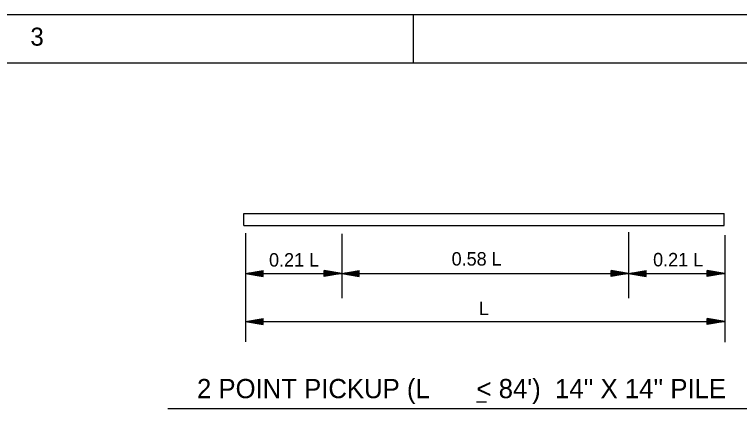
# Model space of a CAD drawing. Extents: x 22369.62 to 22373.29, y 22366.31 to 22369.14.
# Drawn here: x 22371.361 to 22371.989, y 22368.783 to 22369.142 of the extents above; entities that cross this region are included whole.
import ezdxf

# ---------------------------------------------------------------- set-up
doc = ezdxf.new("R2010")
doc.units = 0
for name, color, linetype in [('Level 1', 7, 'Continuous'), ('Level 10', 7, 'Continuous'), ('Level 2', 7, 'Continuous'), ('Level 3', 7, 'Continuous'), ('Level 4', 7, 'Continuous'), ('Level 9', 7, 'Continuous')]:
    doc.layers.add(name, color=color, linetype=linetype)

msp = doc.modelspace()

# ---------------------------------------------------------------- linework, layer by layer
at = {"layer": 'Level 1'}
msp.add_lwpolyline([(22369.6213, 22369.14218), (22373.2867, 22369.14218), (22373.2867, 22366.30818), (22369.6213, 22366.30818)], close=True, dxfattribs=at)
at = {"layer": 'Level 10'}
msp.add_line((22371.7067, 22369.10017), (22371.7067, 22369.14218), dxfattribs=at)
at = {"layer": 'Level 2'}
for p, q in [((22371.55968, 22368.96982), (22371.97617, 22368.96982)), ((22371.55968, 22368.9594), (22371.55968, 22368.96982)), ((22371.97617, 22368.9594), (22371.97617, 22368.96982)), ((22371.55968, 22368.9594), (22371.97617, 22368.9594)), ((22371.76143, 22368.8065), (22371.77014, 22368.8065)), ((22371.49399, 22368.80084), (22372.05537, 22368.80084))]:
    msp.add_line(p, q, dxfattribs=at)
at = {"layer": 'Level 3'}
for p, q in [((22371.56127, 22368.95271), (22371.56127, 22368.85863)), ((22371.64457, 22368.95209), (22371.64457, 22368.89644)), ((22371.8933, 22368.95359), (22371.8933, 22368.89637)), ((22371.9766, 22368.951), (22371.9766, 22368.8583)), ((22371.56127, 22368.91776), (22371.57651, 22368.92034)), ((22371.56127, 22368.91776), (22371.9766, 22368.91776)), ((22371.56127, 22368.91776), (22371.57651, 22368.91776)), ((22371.56127, 22368.91776), (22371.57651, 22368.91516)), ((22371.56406, 22368.91797), (22371.57584, 22368.91997)), ((22371.57619, 22368.91811), (22371.56406, 22368.91797)), ((22371.57619, 22368.91738), (22371.56406, 22368.91753)), ((22371.56406, 22368.91753), (22371.57584, 22368.91554)), ((22371.56741, 22368.91828), (22371.57549, 22368.91961)), ((22371.57582, 22368.91842), (22371.56741, 22368.91828)), ((22371.56741, 22368.91722), (22371.57549, 22368.91588)), ((22371.57582, 22368.91707), (22371.56741, 22368.91722)), ((22371.57065, 22368.91855), (22371.57516, 22368.91924)), ((22371.57548, 22368.91871), (22371.57065, 22368.91855)), ((22371.57065, 22368.91695), (22371.57516, 22368.91626)), ((22371.57548, 22368.9168), (22371.57065, 22368.91695)), ((22371.57518, 22368.91888), (22371.57378, 22368.91882)), ((22371.57518, 22368.91661), (22371.57378, 22368.91668)), ((22371.57516, 22368.91924), (22371.57518, 22368.91888)), ((22371.57549, 22368.91961), (22371.57548, 22368.91871)), ((22371.57549, 22368.91588), (22371.57548, 22368.9168)), ((22371.57584, 22368.91997), (22371.57582, 22368.91842)), ((22371.57584, 22368.91554), (22371.57582, 22368.91707)), ((22371.57618, 22368.91997), (22371.57619, 22368.91811)), ((22371.57618, 22368.91554), (22371.57619, 22368.91738)), ((22371.57651, 22368.91516), (22371.57651, 22368.92034)), ((22371.62933, 22368.91516), (22371.62933, 22368.92034)), ((22371.64457, 22368.91776), (22371.62933, 22368.92034)), ((22371.64457, 22368.91776), (22371.62933, 22368.91776)), ((22371.64457, 22368.91776), (22371.62933, 22368.91516)), ((22371.62966, 22368.91997), (22371.62965, 22368.91811)), ((22371.62965, 22368.91811), (22371.64178, 22368.91797)), ((22371.62965, 22368.91738), (22371.64178, 22368.91753)), ((22371.62966, 22368.91554), (22371.62965, 22368.91738)), ((22371.64178, 22368.91797), (22371.63, 22368.91997)), ((22371.63, 22368.91997), (22371.63002, 22368.91842)), ((22371.64178, 22368.91753), (22371.63, 22368.91554)), ((22371.63, 22368.91554), (22371.63002, 22368.91707)), ((22371.63002, 22368.91842), (22371.63843, 22368.91828)), ((22371.63002, 22368.91707), (22371.63843, 22368.91722)), ((22371.63843, 22368.91828), (22371.63036, 22368.91961)), ((22371.63036, 22368.91961), (22371.63037, 22368.91871)), ((22371.63843, 22368.91722), (22371.63036, 22368.91588)), ((22371.63036, 22368.91588), (22371.63037, 22368.9168)), ((22371.63037, 22368.91871), (22371.63519, 22368.91855)), ((22371.63037, 22368.9168), (22371.63519, 22368.91695)), ((22371.63068, 22368.91924), (22371.63066, 22368.91888)), ((22371.63066, 22368.91888), (22371.63207, 22368.91882)), ((22371.63066, 22368.91661), (22371.63207, 22368.91668)), ((22371.63519, 22368.91855), (22371.63068, 22368.91924)), ((22371.63519, 22368.91695), (22371.63068, 22368.91626)), ((22371.64457, 22368.91776), (22371.65981, 22368.92034)), ((22371.64457, 22368.91776), (22371.65981, 22368.91776)), ((22371.64457, 22368.91776), (22371.65981, 22368.91516)), ((22371.64736, 22368.91797), (22371.65914, 22368.91997)), ((22371.65949, 22368.91811), (22371.64736, 22368.91797)), ((22371.65949, 22368.91738), (22371.64736, 22368.91753)), ((22371.64736, 22368.91753), (22371.65914, 22368.91554)), ((22371.65072, 22368.91828), (22371.65878, 22368.91961)), ((22371.65912, 22368.91842), (22371.65072, 22368.91828)), ((22371.65072, 22368.91722), (22371.65878, 22368.91588)), ((22371.65912, 22368.91707), (22371.65072, 22368.91722)), ((22371.65396, 22368.91855), (22371.65847, 22368.91924)), ((22371.65877, 22368.91871), (22371.65396, 22368.91855)), ((22371.65396, 22368.91695), (22371.65847, 22368.91626)), ((22371.65877, 22368.9168), (22371.65396, 22368.91695)), ((22371.65848, 22368.91888), (22371.65707, 22368.91882)), ((22371.65848, 22368.91661), (22371.65707, 22368.91668)), ((22371.65847, 22368.91924), (22371.65848, 22368.91888)), ((22371.65878, 22368.91961), (22371.65877, 22368.91871)), ((22371.65878, 22368.91588), (22371.65877, 22368.9168)), ((22371.65914, 22368.91997), (22371.65912, 22368.91842)), ((22371.65914, 22368.91554), (22371.65912, 22368.91707)), ((22371.65948, 22368.91997), (22371.65949, 22368.91811)), ((22371.65948, 22368.91554), (22371.65949, 22368.91738)), ((22371.65981, 22368.91516), (22371.65981, 22368.92034)), ((22371.87807, 22368.91516), (22371.87807, 22368.92034)), ((22371.8933, 22368.91776), (22371.87807, 22368.92034)), ((22371.8933, 22368.91776), (22371.87807, 22368.91776)), ((22371.8933, 22368.91776), (22371.87807, 22368.91516)), ((22371.87839, 22368.91997), (22371.87837, 22368.91811)), ((22371.87837, 22368.91811), (22371.89052, 22368.91797)), ((22371.87837, 22368.91738), (22371.89052, 22368.91753)), ((22371.87839, 22368.91554), (22371.87837, 22368.91738)), ((22371.89052, 22368.91797), (22371.87874, 22368.91997)), ((22371.87874, 22368.91997), (22371.87875, 22368.91842)), ((22371.89052, 22368.91753), (22371.87874, 22368.91554)), ((22371.87874, 22368.91554), (22371.87875, 22368.91707)), ((22371.87875, 22368.91842), (22371.88715, 22368.91828)), ((22371.87875, 22368.91707), (22371.88715, 22368.91722)), ((22371.88715, 22368.91828), (22371.87909, 22368.91961)), ((22371.87909, 22368.91961), (22371.8791, 22368.91871)), ((22371.88715, 22368.91722), (22371.87909, 22368.91588)), ((22371.87909, 22368.91588), (22371.8791, 22368.9168)), ((22371.8791, 22368.91871), (22371.8839, 22368.91855)), ((22371.8791, 22368.9168), (22371.8839, 22368.91695)), ((22371.8839, 22368.91855), (22371.8794, 22368.91924)), ((22371.8794, 22368.91924), (22371.8794, 22368.91888)), ((22371.8794, 22368.91888), (22371.8808, 22368.91882)), ((22371.8839, 22368.91695), (22371.8794, 22368.91626)), ((22371.8794, 22368.91661), (22371.8808, 22368.91668)), ((22371.8933, 22368.91776), (22371.90854, 22368.92034)), ((22371.8933, 22368.91776), (22371.90854, 22368.91776)), ((22371.8933, 22368.91776), (22371.90854, 22368.91516)), ((22371.89609, 22368.91797), (22371.90787, 22368.91997)), ((22371.90823, 22368.91811), (22371.89609, 22368.91797)), ((22371.90823, 22368.91738), (22371.89609, 22368.91753)), ((22371.89609, 22368.91753), (22371.90787, 22368.91554)), ((22371.89945, 22368.91828), (22371.90752, 22368.91961)), ((22371.90786, 22368.91842), (22371.89945, 22368.91828)), ((22371.89945, 22368.91722), (22371.90752, 22368.91588)), ((22371.90786, 22368.91707), (22371.89945, 22368.91722)), ((22371.9027, 22368.91855), (22371.9072, 22368.91924)), ((22371.90751, 22368.91871), (22371.9027, 22368.91855)), ((22371.9027, 22368.91695), (22371.9072, 22368.91626)), ((22371.90751, 22368.9168), (22371.9027, 22368.91695)), ((22371.9072, 22368.91888), (22371.9058, 22368.91882)), ((22371.9072, 22368.91661), (22371.9058, 22368.91668)), ((22371.9072, 22368.91924), (22371.9072, 22368.91888)), ((22371.90752, 22368.91961), (22371.90751, 22368.91871)), ((22371.90752, 22368.91588), (22371.90751, 22368.9168)), ((22371.90787, 22368.91997), (22371.90786, 22368.91842)), ((22371.90787, 22368.91554), (22371.90786, 22368.91707)), ((22371.90821, 22368.91997), (22371.90823, 22368.91811)), ((22371.90821, 22368.91554), (22371.90823, 22368.91738)), ((22371.90854, 22368.91516), (22371.90854, 22368.92034)), ((22371.96137, 22368.91516), (22371.96137, 22368.92034)), ((22371.9766, 22368.91776), (22371.96137, 22368.92034)), ((22371.9766, 22368.91776), (22371.96137, 22368.91776)), ((22371.9766, 22368.91776), (22371.96137, 22368.91516)), ((22371.9617, 22368.91997), (22371.96168, 22368.91811)), ((22371.96168, 22368.91811), (22371.97381, 22368.91797)), ((22371.96168, 22368.91738), (22371.97381, 22368.91753)), ((22371.9617, 22368.91554), (22371.96168, 22368.91738)), ((22371.97381, 22368.91797), (22371.96204, 22368.91997)), ((22371.96204, 22368.91997), (22371.96204, 22368.91842)), ((22371.96204, 22368.91842), (22371.97046, 22368.91828)), ((22371.97381, 22368.91753), (22371.96204, 22368.91554)), ((22371.96204, 22368.91707), (22371.97046, 22368.91722)), ((22371.96204, 22368.91554), (22371.96204, 22368.91707)), ((22371.97046, 22368.91828), (22371.96239, 22368.91961)), ((22371.96239, 22368.91961), (22371.9624, 22368.91871)), ((22371.97046, 22368.91722), (22371.96239, 22368.91588)), ((22371.96239, 22368.91588), (22371.9624, 22368.9168)), ((22371.9624, 22368.91871), (22371.96721, 22368.91855)), ((22371.9624, 22368.9168), (22371.96721, 22368.91695)), ((22371.96721, 22368.91855), (22371.96271, 22368.91924)), ((22371.96271, 22368.91924), (22371.96271, 22368.91888)), ((22371.96271, 22368.91888), (22371.9641, 22368.91882)), ((22371.96721, 22368.91695), (22371.96271, 22368.91626)), ((22371.96271, 22368.91661), (22371.9641, 22368.91668)), ((22371.57516, 22368.91626), (22371.57518, 22368.91661)), ((22371.63068, 22368.91626), (22371.63066, 22368.91661)), ((22371.65847, 22368.91626), (22371.65848, 22368.91661)), ((22371.8794, 22368.91626), (22371.8794, 22368.91661)), ((22371.9072, 22368.91626), (22371.9072, 22368.91661)), ((22371.96271, 22368.91626), (22371.96271, 22368.91661)), ((22371.56127, 22368.8761), (22371.57651, 22368.87869)), ((22371.56127, 22368.8761), (22371.9766, 22368.8761)), ((22371.56127, 22368.8761), (22371.57651, 22368.8761)), ((22371.56127, 22368.8761), (22371.57651, 22368.87352)), ((22371.56406, 22368.87632), (22371.57584, 22368.87831)), ((22371.57619, 22368.87647), (22371.56406, 22368.87632)), ((22371.57619, 22368.87574), (22371.56406, 22368.87588)), ((22371.56406, 22368.87588), (22371.57584, 22368.87389)), ((22371.56741, 22368.87663), (22371.57549, 22368.87797)), ((22371.57582, 22368.87678), (22371.56741, 22368.87663)), ((22371.56741, 22368.87557), (22371.57549, 22368.87424)), ((22371.57582, 22368.87543), (22371.56741, 22368.87557)), ((22371.57065, 22368.8769), (22371.57516, 22368.87759)), ((22371.57548, 22368.87705), (22371.57065, 22368.8769)), ((22371.57065, 22368.8753), (22371.57516, 22368.87461)), ((22371.57548, 22368.87514), (22371.57065, 22368.8753)), ((22371.57518, 22368.87724), (22371.57378, 22368.87718)), ((22371.57518, 22368.87497), (22371.57378, 22368.87503)), ((22371.57516, 22368.87759), (22371.57518, 22368.87724)), ((22371.57516, 22368.87461), (22371.57518, 22368.87497)), ((22371.57549, 22368.87797), (22371.57548, 22368.87705)), ((22371.57549, 22368.87424), (22371.57548, 22368.87514)), ((22371.57584, 22368.87831), (22371.57582, 22368.87678)), ((22371.57584, 22368.87389), (22371.57582, 22368.87543)), ((22371.57618, 22368.87831), (22371.57619, 22368.87647)), ((22371.57618, 22368.87389), (22371.57619, 22368.87574)), ((22371.57651, 22368.87352), (22371.57651, 22368.87869)), ((22371.96137, 22368.87352), (22371.96137, 22368.87869)), ((22371.9766, 22368.8761), (22371.96137, 22368.87869)), ((22371.9766, 22368.8761), (22371.96137, 22368.8761)), ((22371.9766, 22368.8761), (22371.96137, 22368.87352)), ((22371.9617, 22368.87831), (22371.96168, 22368.87647)), ((22371.96168, 22368.87647), (22371.97381, 22368.87632)), ((22371.96168, 22368.87574), (22371.97381, 22368.87588)), ((22371.9617, 22368.87389), (22371.96168, 22368.87574)), ((22371.97381, 22368.87632), (22371.96204, 22368.87831)), ((22371.96204, 22368.87831), (22371.96204, 22368.87678)), ((22371.96204, 22368.87678), (22371.97046, 22368.87663)), ((22371.97381, 22368.87588), (22371.96204, 22368.87389)), ((22371.96204, 22368.87543), (22371.97046, 22368.87557)), ((22371.96204, 22368.87389), (22371.96204, 22368.87543)), ((22371.97046, 22368.87663), (22371.96239, 22368.87797)), ((22371.96239, 22368.87797), (22371.9624, 22368.87705)), ((22371.97046, 22368.87557), (22371.96239, 22368.87424)), ((22371.96239, 22368.87424), (22371.9624, 22368.87514)), ((22371.9624, 22368.87705), (22371.96721, 22368.8769)), ((22371.9624, 22368.87514), (22371.96721, 22368.8753)), ((22371.96721, 22368.8769), (22371.96271, 22368.87759)), ((22371.96271, 22368.87759), (22371.96271, 22368.87724)), ((22371.96271, 22368.87724), (22371.9641, 22368.87718)), ((22371.96721, 22368.8753), (22371.96271, 22368.87461)), ((22371.96271, 22368.87497), (22371.9641, 22368.87503)), ((22371.96271, 22368.87461), (22371.96271, 22368.87497))]:
    msp.add_line(p, q, dxfattribs=at)
at = {"layer": 'Level 9'}
msp.add_line((22369.7463, 22369.10017), (22373.0157, 22369.10017), dxfattribs=at)

# ---------------------------------------------------------------- texts
at = {"layer": 'Level 1'}
msp.add_text('3', height=0.01561, dxfattribs=at).set_placement((22371.3747, 22369.11518))
at = {"layer": 'Level 2'}
for s, p in [('2 POINT PICKUP (L', (22371.51915, 22368.80976)), ("< 84')  14'' X 14'' PILE", (22371.76147, 22368.80976))]:
    msp.add_text(s, height=0.0166563, dxfattribs=at).set_placement(p)
at = {"layer": 'Level 4'}
for s, height, p in [('0.21 L', 0.011667, (22371.58158, 22368.92375)), ('0.58 L', 0.011667, (22371.73986, 22368.92464)), ('0.21 L', 0.011667, (22371.9145, 22368.92396)), ('L', 0.01167, (22371.76352, 22368.88179))]:
    msp.add_text(s, height=height, dxfattribs=at).set_placement(p)

doc.saveas('drawing.dxf')
